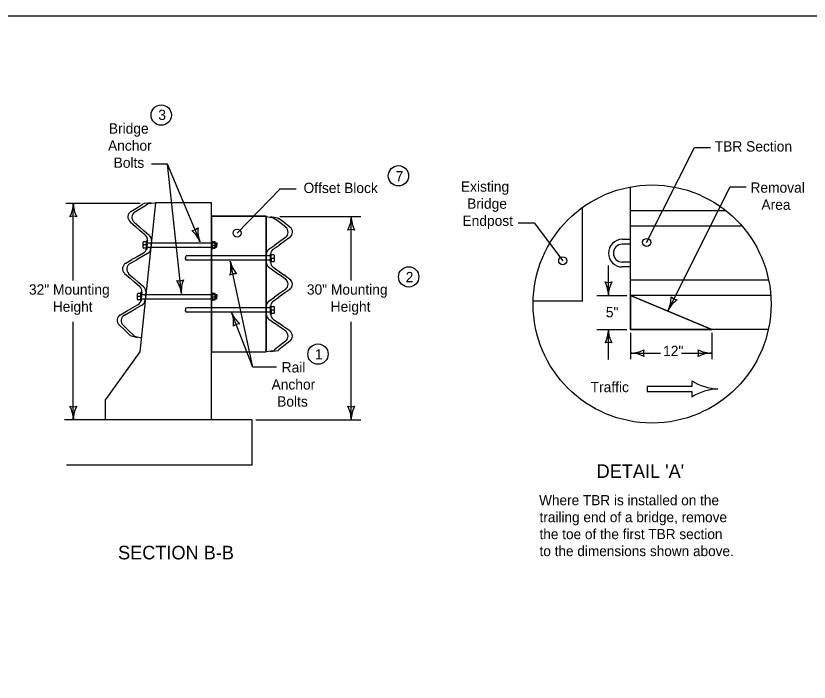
# Model space of a CAD drawing. Extents: x 10028 to 81668, y 3581 to 11018.
# Drawn here: x 18174 to 19344, y 8962 to 9944 of the extents above; entities that cross this region are included whole.
import ezdxf

# ---------------------------------------------------------------- set-up
doc = ezdxf.new("R2010")
doc.units = 0
for name, color, linetype in [('conPaving', 7, 'Continuous'), ('dsnCellsNorthArrow', 7, 'Continuous'), ('dsnTextTabulation', 7, 'Continuous'), ('Level 41', 7, 'Continuous'), ('Level 9', 7, 'Continuous'), ('SheetBorder', 7, 'Continuous')]:
    doc.layers.add(name, color=color, linetype=linetype)

msp = doc.modelspace()

# ---------------------------------------------------------------- linework, layer by layer
at = {"layer": 'conPaving'}
for p, q in [((18469, 9609.4), (18468.5, 9603)), ((18469.6, 9609.4), (18469.1, 9603)), ((18470.1, 9609.4), (18469.6, 9603)), ((18470.7, 9609.4), (18470.2, 9603)), ((18469, 9533.3), (18468.5, 9526.8)), ((18469.5, 9533.3), (18469, 9526.8)), ((18470.1, 9533.3), (18469.6, 9526.8)), ((18470.6, 9533.3), (18470.1, 9526.8))]:
    msp.add_line(p, q, dxfattribs=at)
at = {"layer": 'dsnCellsNorthArrow'}
for p, q in [((18380, 9668.4), (18357.2, 9448.6)), ((18462.6, 9668.4), (18380, 9668.4)), ((18462.6, 9348.6), (18462.6, 9668.4)), ((18357.2, 9448.6), (18306.6, 9378.6)), ((18306.6, 9348.6), (18306.6, 9378.6))]:
    msp.add_line(p, q, dxfattribs=at)
at = {"layer": 'dsnTextTabulation'}
for p, q in [((19104.6, 9610), (19175, 9750.1)), ((19175, 9750.1), (19198.6, 9750.1)), ((18397.6, 9725.6), (18374, 9725.6)), ((18445.8, 9610.9), (18397.6, 9725.6)), ((18418.3, 9534.5), (18397.6, 9725.6)), ((18500.5, 9623.8), (18563.9, 9688.9)), ((18563.9, 9688.9), (18587.6, 9688.9)), ((19080.7, 9481.8), (19080.7, 9691.8)), ((19136.1, 9509.8), (19227.6, 9692)), ((19227.6, 9692), (19251.2, 9692)), ((18247.8, 9667.8), (18357.7, 9667.8)), ((18353.4, 9661.5), (18360.9, 9666.2)), ((18359.3, 9660.9), (18366.9, 9665.6)), ((18363.2, 9667.6), (18360.9, 9666.2)), ((18373.9, 9668.4), (18363.2, 9667.6)), ((18369.1, 9667), (18366.9, 9665.6)), ((18379.8, 9667.8), (18369.1, 9667)), ((18258.9, 9554), (18258.9, 9661.9)), ((18343.8, 9655.6), (18353.4, 9661.5)), ((18349.8, 9654.9), (18359.3, 9660.9)), ((19221.9, 9656.6), (19080.7, 9656.6)), ((18543.6, 9648.3), (18554.2, 9646.4)), ((18550, 9648.3), (18560.6, 9646.4)), ((18554.2, 9646.4), (18556.3, 9644.8)), ((18563.3, 9639.3), (18556.3, 9644.8)), ((18560.6, 9646.4), (18562.7, 9644.8)), ((18569.7, 9639.3), (18562.7, 9644.8)), ((18563.3, 9648.2), (18683.2, 9648.2)), ((18668.8, 9554), (18668.8, 9648.2)), ((18342.6, 9640.5), (18350.4, 9633.7)), ((18348.6, 9639.9), (18356.3, 9633.1)), ((18350.4, 9633.7), (18357.1, 9627.8)), ((18356.3, 9633.1), (18363, 9627.2)), ((18572.2, 9632.4), (18563.3, 9639.3)), ((18578.5, 9632.4), (18569.7, 9639.3)), ((18915.2, 9639.1), (18938.8, 9639.1)), ((18938.8, 9639.1), (18980.8, 9583)), ((19245.3, 9634.1), (19080.7, 9634.1)), ((18365, 9620.8), (18357.1, 9627.8)), ((18371, 9620.1), (18363, 9627.2)), ((18367.6, 9607.3), (18367.3, 9603.5)), ((18367.6, 9607.1), (18368, 9611)), ((18368.2, 9612.7), (18368, 9611)), ((18373.6, 9606.6), (18373.2, 9602.9)), ((18373.6, 9606.5), (18374, 9610.4)), ((18374.2, 9612.1), (18374, 9610.4)), ((18563.4, 9611.3), (18556.1, 9606.2)), ((18569.8, 9611.3), (18562.5, 9606.2)), ((18571.8, 9617.3), (18563.4, 9611.3)), ((18578.2, 9617.3), (18569.8, 9611.3)), ((18367, 9601.5), (18367.3, 9603.5)), ((18373, 9600.9), (18373.2, 9602.9)), ((18547.4, 9600), (18556.1, 9606.2)), ((18553.8, 9600), (18562.5, 9606.2)), ((18336.4, 9579.5), (18345.4, 9584.6)), ((18342.3, 9578.8), (18351.4, 9584)), ((18353.1, 9589), (18345.4, 9584.6)), ((18359.1, 9588.4), (18351.4, 9584)), ((18362.3, 9594.3), (18353.1, 9589)), ((18368.3, 9593.6), (18359.1, 9588.4)), ((18543.5, 9586.8), (18543.4, 9583.1)), ((18543.4, 9581), (18543.4, 9583.1)), ((18543.5, 9592.4), (18543.5, 9590.6)), ((18543.5, 9586.7), (18543.5, 9590.6)), ((18549.9, 9586.8), (18549.8, 9583.1)), ((18549.8, 9581), (18549.8, 9583.1)), ((18549.9, 9592.4), (18549.9, 9590.6)), ((18549.9, 9586.7), (18549.9, 9590.6)), ((18523.8, 9426.2), (18490.4, 9582.3)), ((18547.4, 9573.4), (18556, 9567.2)), ((18553.8, 9573.4), (18562.4, 9567.2)), ((19048.2, 9531.8), (19048.2, 9576.1)), ((18334.6, 9564.4), (18342.6, 9557.4)), ((18340.5, 9563.8), (18348.6, 9556.7)), ((18556, 9567.2), (18563.2, 9562)), ((18562.4, 9567.2), (18569.6, 9562)), ((18571.7, 9555.9), (18563.2, 9562)), ((18578, 9555.9), (18569.6, 9562)), ((18342.6, 9557.4), (18349.3, 9551.5)), ((18348.6, 9556.7), (18355.3, 9550.9)), ((18357, 9544.7), (18349.3, 9551.5)), ((18363, 9544.1), (18355.3, 9550.9)), ((19284.6, 9554.2), (19080.7, 9554.2)), ((18360.2, 9536.7), (18360, 9535.1)), ((18571.9, 9540.8), (18563.2, 9534.6)), ((18578.3, 9540.8), (18569.6, 9534.6)), ((18359, 9525.4), (18359.2, 9527.6)), ((18359.6, 9531.4), (18359.2, 9527.6)), ((18359.6, 9531.4), (18360, 9535.1)), ((18365, 9524.8), (18365.2, 9527)), ((18365.6, 9530.7), (18365.2, 9527)), ((18365.6, 9530.7), (18366, 9534.5)), ((18366.1, 9536), (18366, 9534.5)), ((18547.5, 9523.5), (18555.9, 9529.5)), ((18553.9, 9523.5), (18562.3, 9529.5)), ((18563.2, 9534.6), (18555.9, 9529.5)), ((18569.6, 9534.6), (18562.3, 9529.5)), ((19030.9, 9531.8), (19075.2, 9531.8)), ((19287.7, 9531.8), (19080.7, 9531.8)), ((18337.6, 9508.7), (18345.4, 9513.1)), ((18354.3, 9518.2), (18345.4, 9513.1)), ((18360.3, 9517.6), (18351.3, 9512.5)), ((18543.6, 9515.9), (18543.5, 9514.3)), ((18543.5, 9510.5), (18543.5, 9514.3)), ((18549.9, 9515.9), (18549.9, 9514.3)), ((18549.9, 9510.5), (18549.9, 9514.3)), ((18328.3, 9503.4), (18337.6, 9508.7)), ((18334.3, 9502.8), (18343.6, 9508.1)), ((18343.6, 9508.1), (18351.3, 9512.5)), ((18523.8, 9426.2), (18492.3, 9506.8)), ((18543.5, 9510.5), (18543.5, 9506.8)), ((18543.5, 9504.6), (18543.5, 9506.8)), ((18549.9, 9510.5), (18549.9, 9506.8)), ((18549.9, 9504.6), (18549.9, 9506.8)), ((18258.9, 9348.5), (18258.9, 9493)), ((18547.5, 9496.9), (18555.8, 9490.9)), ((18553.9, 9496.9), (18562.2, 9490.9)), ((18563, 9485.7), (18555.8, 9490.9)), ((18569.4, 9485.7), (18562.2, 9490.9)), ((18668.8, 9348.5), (18668.8, 9493)), ((18326.5, 9488.4), (18334.9, 9480.4)), ((18332.5, 9487.8), (18340.8, 9479.8)), ((18334.9, 9480.4), (18341.3, 9474.3)), ((18340.8, 9479.8), (18347.3, 9473.6)), ((18571.7, 9479.5), (18563, 9485.7)), ((18578.1, 9479.5), (18569.4, 9485.7)), ((19030.9, 9481.8), (19075.2, 9481.8)), ((19048.2, 9437.5), (19048.2, 9481.8)), ((19284.1, 9481.8), (19080.7, 9481.8)), ((18343, 9472.7), (18341.3, 9474.3)), ((18343, 9472.7), (18353.3, 9469.8)), ((18349, 9472), (18347.3, 9473.6)), ((18349, 9472), (18359.3, 9469.1)), ((19080.7, 9476.9), (19080.7, 9437.7)), ((19200.5, 9476.9), (19200.5, 9437.7)), ((18562.8, 9457.3), (18555.8, 9451.8)), ((18569.2, 9457.3), (18562.2, 9451.8)), ((18572, 9464.4), (18562.8, 9457.3)), ((18578.4, 9464.4), (18569.2, 9457.3)), ((18554, 9450.4), (18543.4, 9448.6)), ((18560.4, 9450.4), (18549.8, 9448.6)), ((18554, 9450.4), (18555.8, 9451.8)), ((18560.4, 9450.4), (18562.2, 9451.8)), ((19080.7, 9446.8), (19125.1, 9446.8)), ((19156.1, 9446.8), (19200.5, 9446.8)), ((18558.6, 9426.2), (18523.8, 9426.2)), ((18528.1, 9348.5), (18683.2, 9348.5))]:
    msp.add_line(p, q, dxfattribs=at)
for centre in [(18388.6, 9797.8), (18738.5, 9708.2), (18753.6, 9559.2), (18619.8, 9445.3)]:
    msp.add_circle(centre, 15, dxfattribs=at)
for centre, radius, start, end in [((18216.4, 9667.8), 42.5, 331.9275, 360), ((18301.4, 9667.8), 42.5, 180, 208.0725), ((18258.9, 9632.1), 16.4, 72.2666, 107.7334), ((18626.3, 9648.2), 42.5, 331.9275, 360), ((18711.3, 9648.2), 42.5, 180, 208.0725), ((18432.3, 9643.9), 16.4, 274.4291, 309.8958), ((18485.1, 9627), 42.5, 174.09, 202.1625), ((18406.4, 9594.9), 42.5, 22.1625, 50.235), ((18668.8, 9612.6), 16.4, 72.2666, 107.7334), ((18449, 9573), 42.5, 344.5421, 12.6146), ((18531.9, 9591.5), 42.5, 192.6146, 220.6871), ((18498.2, 9547.5), 16.4, 84.8812, 120.3479), ((18414.8, 9569.9), 16.4, 257.8046, 293.2713), ((18376, 9530.4), 42.5, 5.538, 33.6104), ((18460.6, 9538.6), 42.5, 157.4655, 185.538), ((19048.2, 9567.4), 16.4, 252.2666, 287.7334), ((19005.7, 9531.8), 42.5, 0, 28.0725), ((19048.2, 9567.4), 16.4, 252.2666, 287.7334), ((19005.7, 9531.8), 42.5, 0, 28.0725), ((19090.7, 9531.8), 42.5, 151.9275, 180), ((19090.7, 9531.8), 42.5, 151.9275, 180), ((19098.2, 9529), 42.5, 333.1429, 1.2154), ((19174, 9490.6), 42.5, 125.0704, 153.1429), ((19152.2, 9541.5), 16.4, 225.4095, 260.8762), ((18452.9, 9491), 42.5, 353.7829, 21.8554), ((18531.8, 9522.7), 42.5, 201.8554, 229.9279), ((18505.6, 9473.8), 16.4, 94.122, 129.5887), ((19005.7, 9481.8), 42.5, 331.9275, 0), ((19005.7, 9481.8), 42.5, 331.9275, 0), ((19090.7, 9481.8), 42.5, 180, 208.0725), ((19090.7, 9481.8), 42.5, 180, 208.0725), ((19048.2, 9446.2), 16.4, 72.2666, 107.7334), ((19048.2, 9446.2), 16.4, 72.2666, 107.7334), ((19080.7, 9489.3), 42.5, 270, 298.0725), ((19080.7, 9489.3), 42.5, 270, 298.0725), ((19080.7, 9404.3), 42.5, 61.9275, 90), ((19080.7, 9404.3), 42.5, 61.9275, 90), ((19116.3, 9446.8), 16.4, 162.2666, 197.7334), ((19116.3, 9446.8), 16.4, 162.2666, 197.7334), ((19164.8, 9446.8), 16.4, 342.2667, 17.7334), ((19200.5, 9489.3), 42.5, 241.9275, 270), ((19164.8, 9446.8), 16.4, 342.2667, 17.7334), ((19200.5, 9489.3), 42.5, 241.9275, 270), ((19200.5, 9404.3), 42.5, 90, 118.0725), ((19200.5, 9404.3), 42.5, 90, 118.0725), ((18258.9, 9384.2), 16.4, 252.2666, 287.7333), ((18216.4, 9348.5), 42.5, 360, 28.0725), ((18301.4, 9348.5), 42.5, 151.9275, 180), ((18668.8, 9384.2), 16.4, 252.2666, 287.7333), ((18626.3, 9348.5), 42.5, 360, 28.0725), ((18711.3, 9348.5), 42.5, 151.9275, 180)]:
    msp.add_arc(centre, radius, start, end, dxfattribs=at)
for centre, major_axis, start_param, end_param in [((18348.9, 9647.6), (9.43, -0.96), 2.229659, 4.096128), ((18354.8, 9647), (9.43, -0.96), 2.229659, 4.096128), ((18566.3, 9625), (-9.48, 0.02), 2.187057, 4.053527), ((18572.7, 9625), (-9.48, 0.02), 2.187057, 4.053527), ((18358.8, 9613.7), (9.43, -0.96), 0, 0.954538), ((18364.7, 9613.1), (9.43, -0.96), 0, 0.954538), ((18357.6, 9602.4), (-9.43, 0.96), 2.187055, 3.141593), ((18363.6, 9601.8), (-9.43, 0.96), 2.187055, 3.141593), ((18552.9, 9592.3), (-9.48, 0.02), 5.328647, 6.283185), ((18559.3, 9592.3), (-9.48, 0.02), 5.328647, 6.283185), ((18341.1, 9571.3), (-9.43, 0.96), 5.32865, 7.195119), ((18347.1, 9570.6), (-9.43, 0.96), 5.32865, 7.195119), ((18552.9, 9581), (9.48, -0.02), 3.141593, 4.096131), ((18559.3, 9581), (9.48, -0.02), 3.141593, 4.096131), ((18566.1, 9548.3), (9.48, -0.02), 5.371251, 7.237721), ((18572.5, 9548.3), (9.48, -0.02), 5.371251, 7.237721), ((18350.7, 9537.6), (9.43, -0.96), 0, 0.954538), ((18356.7, 9537), (9.43, -0.96), 0, 0.954538), ((18349.6, 9526.4), (-9.43, 0.96), 2.187055, 3.141593), ((18355.5, 9525.8), (-9.43, 0.96), 2.187055, 3.141593), ((18553, 9515.8), (-9.48, 0.02), 5.328647, 6.283185), ((18559.4, 9515.8), (-9.48, 0.02), 5.328647, 6.283185), ((18333.1, 9495.2), (-9.43, 0.96), 5.32865, 7.195119), ((18339, 9494.6), (-9.43, 0.96), 5.32865, 7.195119), ((18553, 9504.5), (9.48, -0.02), 3.141593, 4.096131), ((18559.4, 9504.5), (9.48, -0.02), 3.141593, 4.096131), ((18566.2, 9471.8), (9.48, -0.02), 5.371251, 7.237721), ((18572.6, 9471.8), (9.48, -0.02), 5.371251, 7.237721)]:
    msp.add_ellipse(centre, major_axis=major_axis, ratio=0.994906, start_param=start_param, end_param=end_param, dxfattribs=at)
at = {"layer": 'Level 41'}
for p, q in [((19080.7, 9614.5), (19068.7, 9614.5)), ((19080.7, 9607.3), (19068.7, 9607.3)), ((19080.7, 9581), (19068.7, 9581)), ((19080.7, 9573.8), (19068.7, 9573.8))]:
    msp.add_line(p, q, dxfattribs=at)
for radius in [20.4, 13.2]:
    msp.add_arc((19068.7, 9594.2), radius, 90, 270, dxfattribs=at)
at = {"layer": 'Level 9'}
for p, q in [((19009.8, 9523.4), (19009.8, 9661.5)), ((18462.6, 9648.5), (18543.5, 9648.5)), ((18543.5, 9648.5), (18462.6, 9648.5)), ((18462.6, 9648.5), (18462.6, 9448.5)), ((18543.5, 9448.5), (18543.5, 9648.5)), ((18543.5, 9648.5), (18543.5, 9448.5)), ((18362.1, 9605.4), (18362.1, 9610.3)), ((18363, 9611.2), (18366.9, 9611.2)), ((18366.9, 9606.3), (18366.9, 9612.4)), ((18367.8, 9612.4), (18366.9, 9612.4)), ((18366.9, 9601.4), (18366.9, 9611.2)), ((18367.8, 9600.2), (18367.8, 9612.4)), ((18367.8, 9606.3), (18367.8, 9609.5)), ((18367.8, 9609.5), (18470.7, 9609.4)), ((18462.6, 9600.1), (18462.6, 9612.3)), ((18462.6, 9612.3), (18463.5, 9612.3)), ((18462.6, 9606.2), (18462.6, 9609.4)), ((18463.5, 9606.2), (18463.5, 9612.3)), ((18463.5, 9601.3), (18463.5, 9611.1)), ((18467.3, 9611.1), (18463.5, 9611.1)), ((18468.3, 9605.3), (18468.3, 9610.2)), ((18362.1, 9602.3), (18362.1, 9605.4)), ((18366.9, 9606.3), (18363, 9606.3)), ((18366.9, 9601.4), (18363, 9601.4)), ((18366.9, 9606.3), (18366.9, 9600.2)), ((18366.9, 9600.2), (18367.8, 9600.2)), ((18367.8, 9603.1), (18470.2, 9603)), ((18463.5, 9600.1), (18462.6, 9600.1)), ((18463.5, 9606.2), (18463.5, 9600.1)), ((18463.5, 9606.2), (18467.3, 9606.2)), ((18463.5, 9601.3), (18467.3, 9601.4)), ((18468.3, 9602.2), (18468.3, 9605.3)), ((18424.2, 9588.5), (18425.4, 9590.1)), ((18424.2, 9588.5), (18424.2, 9586.9)), ((18424.2, 9585.3), (18424.2, 9586.9)), ((18424.2, 9585.3), (18425.4, 9583.6)), ((18549.8, 9583.6), (18425.3, 9583.8)), ((18549.9, 9590.1), (18425.6, 9590.3)), ((18549.8, 9580.8), (18549.9, 9592.9)), ((18549.9, 9592.9), (18550.8, 9592.9)), ((18549.9, 9586.8), (18549.9, 9590.1)), ((18550.7, 9582), (18550.8, 9591.7)), ((18550.8, 9586.8), (18550.7, 9580.8)), ((18550.8, 9586.8), (18550.8, 9592.9)), ((18554.6, 9591.7), (18550.8, 9591.7)), ((18550.8, 9586.8), (18554.6, 9586.8)), ((18555.5, 9582.8), (18555.6, 9586)), ((18555.6, 9586), (18555.6, 9590.8)), ((18550.7, 9580.8), (18549.8, 9580.8)), ((18550.7, 9582), (18554.6, 9582)), ((18353.7, 9529.3), (18353.7, 9534.1)), ((18353.7, 9526.1), (18353.7, 9529.3)), ((18354.6, 9535), (18358.5, 9535)), ((18358.5, 9530.1), (18354.6, 9530.1)), ((18358.5, 9525.3), (18354.6, 9525.3)), ((18358.5, 9530.1), (18358.5, 9536.2)), ((18359.4, 9536.2), (18358.5, 9536.2)), ((18358.5, 9525.3), (18358.5, 9535)), ((18358.5, 9530.1), (18358.5, 9524.1)), ((18359.4, 9524.1), (18359.4, 9536.2)), ((18359.4, 9530.1), (18359.4, 9533.4)), ((18359.4, 9533.4), (18470.6, 9533.3)), ((18359.4, 9526.9), (18470.1, 9526.8)), ((18462.6, 9524), (18462.6, 9536.1)), ((18462.6, 9536.1), (18463.5, 9536.1)), ((18462.6, 9530), (18462.6, 9533.3)), ((18463.5, 9530), (18463.5, 9536.1)), ((18463.5, 9525.2), (18463.5, 9534.9)), ((18467.3, 9534.9), (18463.5, 9534.9)), ((18463.5, 9530), (18463.5, 9524)), ((18463.5, 9530), (18467.3, 9530)), ((18463.5, 9525.2), (18467.3, 9525.2)), ((18468.3, 9529.2), (18468.3, 9534)), ((18468.3, 9526), (18468.3, 9529.2)), ((18358.5, 9524.1), (18359.4, 9524.1)), ((18424.4, 9512), (18425.6, 9513.6)), ((18550, 9513.6), (18425.7, 9513.8)), ((18463.5, 9524), (18462.6, 9524)), ((18550, 9504.3), (18550, 9516.5)), ((18550, 9516.5), (18550.9, 9516.5)), ((18550, 9510.4), (18550, 9513.6)), ((18550.9, 9510.4), (18550.9, 9516.5)), ((18550.9, 9505.5), (18550.9, 9515.2)), ((18554.7, 9515.2), (18550.9, 9515.2)), ((18555.7, 9509.5), (18555.7, 9514.4)), ((19009.8, 9523.4), (18937.1, 9523.4)), ((18424.4, 9512), (18424.4, 9510.4)), ((18424.4, 9508.8), (18424.4, 9510.4)), ((18424.4, 9508.8), (18425.5, 9507.2)), ((18550, 9507.1), (18425.4, 9507.4)), ((18550.9, 9504.3), (18550, 9504.3)), ((18550.9, 9510.4), (18550.9, 9504.3)), ((18550.9, 9510.4), (18554.7, 9510.4)), ((18550.9, 9505.5), (18554.7, 9505.5)), ((18555.7, 9506.4), (18555.7, 9509.5)), ((18462.6, 9448.5), (18543.5, 9448.5)), ((18462.6, 9448.5), (18543.5, 9448.5)), ((19171.3, 9397.6), (19105.3, 9397.6)), ((19105.3, 9397.6), (19105.3, 9390.4)), ((19171.3, 9406), (19171.3, 9397.6)), ((19105.3, 9390.4), (19171.3, 9390.4)), ((19171.3, 9390.4), (19171.3, 9382)), ((19209.6, 9394), (19209.6, 9394)), ((18522, 9348.5), (18246.1, 9348.5)), ((18522, 9348.5), (18522, 9281.5)), ((18522, 9281.5), (18249, 9281.5))]:
    msp.add_line(p, q, dxfattribs=at)
msp.add_lwpolyline([(19080.7, 9481.8), (19200.5, 9481.8), (19080.7, 9531.8), (19080.7, 9481.8)], dxfattribs=at)
msp.add_lwpolyline([(19080.7, 9531.8), (19200.5, 9481.8), (19080.7, 9481.8)], close=True, dxfattribs=at)
for centre, radius in [((19112.6, 9519.2), 175.5), ((18500.5, 9623.8), 5.96), ((19104.6, 9610), 5.96), ((18980.8, 9583), 5.96)]:
    msp.add_circle(centre, radius, dxfattribs=at)
for centre, start, end in [((19212.8, 9471.3), 237.618, 267.648), ((19212.8, 9316.7), 92.352, 122.382)]:
    msp.add_arc(centre, 77.4, start, end, dxfattribs=at)
for centre, major_axis, start_param, end_param in [((18363, 9610.3), (-0.96, 0.001), 4.712389, 6.283185), ((18363, 9607.2), (-0.96, 0.001), 0, 1.570796), ((18467.3, 9610.2), (-0.96, -0.001), 3.141593, 4.712389), ((18467.3, 9607.1), (-0.96, -0.001), 1.570796, 3.141593), ((18363, 9605.4), (-0.96, 0.001), 4.712389, 6.283185), ((18363, 9602.3), (-0.96, 0.001), 6.283185, 7.853982), ((18467.3, 9605.3), (-0.96, -0.001), 3.141593, 4.712389), ((18467.3, 9602.2), (-0.96, -0.001), 1.570796, 3.141593), ((18554.6, 9590.8), (-0.96, 0.002), 3.141593, 4.712389), ((18554.6, 9587.7), (-0.96, 0.002), 1.570796, 3.141593), ((18554.6, 9586), (-0.96, 0.002), 3.141593, 4.712389), ((18554.6, 9582.8), (-0.96, 0.002), 1.570796, 3.141593), ((18354.6, 9534.1), (-0.96, 0.001), 4.712389, 6.283185), ((18354.6, 9531), (-0.96, 0.001), 0, 1.570796), ((18354.6, 9529.3), (-0.96, 0.001), 4.712389, 6.283185), ((18354.6, 9526.1), (-0.96, 0.001), 6.283185, 7.853982), ((18467.3, 9534), (-0.96, -0.001), 3.141593, 4.712389), ((18467.3, 9530.9), (-0.96, -0.001), 1.570796, 3.141593), ((18467.3, 9529.2), (-0.96, -0.001), 3.141593, 4.712389), ((18467.3, 9526), (-0.96, -0.001), 1.570796, 3.141593), ((18554.7, 9514.4), (-0.96, 0.002), 3.141593, 4.712389), ((18554.7, 9511.2), (-0.96, 0.002), 1.570796, 3.141593), ((18554.7, 9509.5), (-0.96, 0.002), 3.141593, 4.712389), ((18554.7, 9506.4), (-0.96, 0.002), 1.570796, 3.141593)]:
    msp.add_ellipse(centre, major_axis=major_axis, ratio=0.899999, start_param=start_param, end_param=end_param, dxfattribs=at)
at = {"layer": 'SheetBorder'}
msp.add_lwpolyline([(17332.5, 9944), (20467.5, 9944), (20467.5, 7924), (17332.5, 7924)], close=True, dxfattribs=at)

# ---------------------------------------------------------------- texts
at = {"layer": 'dsnCellsNorthArrow'}
for s, height, p in [('Bridge', 15.2, (18311.3, 9770.4)), ('Anchor', 15.2, (18310.1, 9745.2)), ('TBR Section', 15.2, (19205, 9744)), ('Bolts', 15.2, (18318.4, 9720)), ('Existing', 15.2, (18830.6, 9684.8)), ('Offset Block', 15.2, (18598.5, 9682.8)), ('Removal', 15.2, (19257.7, 9683.3)), ('Bridge', 15.2, (18839.8, 9659.6)), ('Area', 15.2, (19273.9, 9658.1)), ('Endpost', 15.2, (18832.9, 9634.4)), ('32" Mounting', 15.2, (18193.5, 9533)), ('30" Mounting', 15.2, (18603.4, 9533)), ('Height', 15.2, (18228.6, 9507.8)), ('Height', 15.2, (18638.5, 9507.8)), ('5"', 15.2, (19044.4, 9499.6)), ('12"', 15.2, (19128.9, 9442.4)), ('Rail', 15.2, (18566.2, 9418.3)), ('Anchor', 15.2, (18551.3, 9393.1)), ('Traffic', 15.2, (19022, 9389.2)), ('Bolts', 15.2, (18559.6, 9367.9)), ("DETAIL 'A'", 20, (19030.8, 9262.8)), ('SECTION B-B', 20, (18324.9, 9142.7))]:
    msp.add_text(s, height=height, dxfattribs=at).set_placement(p)
at = {"layer": 'dsnTextTabulation'}
for s, p in [('3', (18384.3, 9790.5)), ('7', (18734.3, 9699.9)), ('2', (18749.2, 9551.3)), ('1', (18615.4, 9437.4))]:
    msp.add_text(s, height=15.2, dxfattribs=at).set_placement(p)
at = {"layer": 'Level 9'}
for s, p in [('Where TBR is installed on the ', (18946, 9222.5)), ('trailing end of a bridge, remove ', (18946.6, 9197.5)), ('the toe of the first TBR section ', (18946.6, 9172.5)), ('to the dimensions shown above.', (18946.6, 9147.5))]:
    msp.add_text(s, height=15, dxfattribs=at).set_placement(p)

doc.saveas('drawing.dxf')
